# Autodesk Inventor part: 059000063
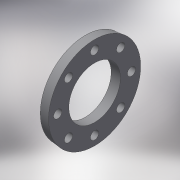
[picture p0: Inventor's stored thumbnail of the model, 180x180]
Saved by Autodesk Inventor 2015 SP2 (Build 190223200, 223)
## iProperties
Created: 2017-10
Part Number: 059000063
Material: Generic
Description: PLASSON BACKING FLANGE PVC 63
Document SubType Name: Modeling
Designer: KIM
Density: 1 g/cm^3
Appearance: Default
Author: KIM
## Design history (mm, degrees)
derived "059000.ipt"
feature "Solid1::059000.ipt"
tag "TaggingFeature1"
body "Solid1"
other parameters: "d0" = 18, "d2" = 165, "d3" = 161.7, "d5" = 18, "d6" = 62.5, "d7" = 18, "d8" = 0, "d10" = 360 deg, "D_" = 63, "E_1" = 165, "H_" = 18, "Dp_" = 125, "S_" = 18
